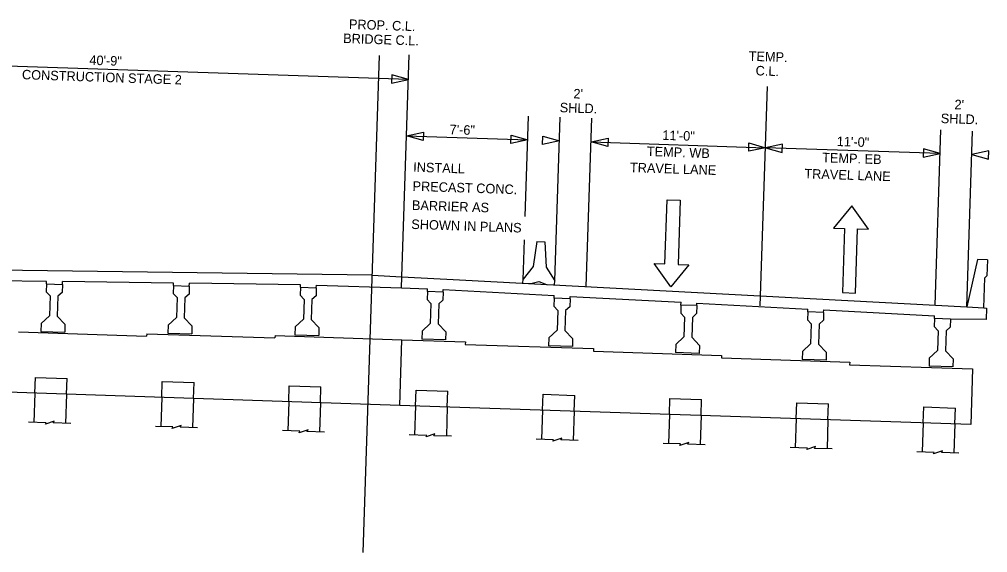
# Model space of a CAD drawing. Extents: x 977258 to 978774, y 1525946 to 1526932.
# Drawn here: x 977645 to 978255, y 1526136 to 1526472 of the extents above; entities that cross this region are included whole.
import ezdxf

# ---------------------------------------------------------------- set-up
doc = ezdxf.new("R2010")
doc.units = 0
for name, color, linetype in [('B_County and Route', 7, 'Continuous'), ('BDR_Plan Profile Grid 1', 7, 'Continuous'), ('BDR_Plan Profile Grid 5', 7, 'Continuous'), ('BDR_Plan Profile Grid 6', 7, 'Continuous'), ('Default', 7, 'Continuous'), ('R_Border', 7, 'Continuous'), ('R_MOT', 7, 'Continuous'), ('STAMP_PP', 7, 'Continuous')]:
    doc.layers.add(name, color=color, linetype=linetype)

msp = doc.modelspace()

# ---------------------------------------------------------------- linework, layer by layer
at = {"layer": 'B_County and Route'}
for p, q in [((977861.46, 1526135.95), (977871.9, 1526448.95)), ((978111.78, 1526291.34), (978116.39, 1526429.43))]:
    msp.add_line(p, q, dxfattribs=at)
at = {"layer": 'BDR_Plan Profile Grid 1'}
for p, q in [((977661.69, 1526217.73), (977650.75, 1526218.1)), ((977666.88, 1526218.68), (977661.27, 1526216.79)), ((977661.27, 1526216.79), (977661.69, 1526217.73)), ((977666.18, 1526217.58), (977666.88, 1526218.68)), ((977677.24, 1526217.21), (977666.18, 1526217.58)), ((977741.64, 1526215.07), (977730.71, 1526215.43)), ((977746.84, 1526216.01), (977741.23, 1526214.12)), ((977741.23, 1526214.12), (977741.64, 1526215.07)), ((977746.14, 1526214.92), (977746.84, 1526216.01)), ((977757.2, 1526214.55), (977746.14, 1526214.92)), ((977821.6, 1526212.4), (977810.67, 1526212.76)), ((977826.79, 1526213.35), (977821.18, 1526211.45)), ((977821.18, 1526211.45), (977821.6, 1526212.4)), ((977826.09, 1526212.25), (977826.79, 1526213.35)), ((977837.15, 1526211.88), (977826.09, 1526212.25))]:
    msp.add_line(p, q, dxfattribs=at)
at = {"layer": 'BDR_Plan Profile Grid 5'}
for p, q in [((978248.66, 1526320.45), (978241.83, 1526290.66)), ((978254.91, 1526320.24), (978248.66, 1526320.45)), ((978254.91, 1526320.24), (978254.57, 1526310.25)), ((977867.29, 1526310.65), (977492.25, 1526315.66)), ((977662.04, 1526306.73), (977592.03, 1526307.66)), ((977661.99, 1526305.16), (977662.04, 1526306.73)), ((977671.98, 1526304.83), (977672.04, 1526306.59)), ((977742.05, 1526305.66), (977672.04, 1526306.59)), ((977742, 1526304.09), (977742.05, 1526305.66)), ((977751.99, 1526303.76), (977752.05, 1526305.53)), ((977822.06, 1526304.59), (977752.05, 1526305.53)), ((977867.29, 1526310.65), (977885.93, 1526309.66)), ((977885.93, 1526309.66), (977922.22, 1526307.72)), ((977922.22, 1526307.72), (978241.83, 1526290.66)), ((978252.65, 1526290.08), (978253.28, 1526309.04)), ((978254.57, 1526310.25), (978253.28, 1526309.04)), ((977661.99, 1526305.16), (977661.82, 1526300.16)), ((977661.99, 1526305.16), (977661.82, 1526300.16)), ((977661.82, 1526300.16), (977664.24, 1526297.58)), ((977661.82, 1526300.16), (977664.24, 1526297.58)), ((977661.99, 1526305.16), (977671.98, 1526304.83)), ((977661.99, 1526305.16), (977671.98, 1526304.83)), ((977671.82, 1526299.83), (977669.24, 1526297.41)), ((977671.82, 1526299.83), (977669.24, 1526297.41)), ((977671.98, 1526304.83), (977671.82, 1526299.83)), ((977671.98, 1526304.83), (977671.82, 1526299.83)), ((977671.98, 1526304.83), (977671.82, 1526299.83)), ((977671.98, 1526304.83), (977671.82, 1526299.83)), ((977742, 1526304.09), (977741.83, 1526299.1)), ((977742, 1526304.09), (977741.83, 1526299.1)), ((977742, 1526304.09), (977751.99, 1526303.76)), ((977742, 1526304.09), (977751.99, 1526303.76)), ((977751.99, 1526303.76), (977751.83, 1526298.76)), ((977751.99, 1526303.76), (977751.83, 1526298.76)), ((977751.99, 1526303.76), (977751.83, 1526298.76)), ((977751.99, 1526303.76), (977751.83, 1526298.76)), ((977822.01, 1526303.03), (977821.84, 1526298.03)), ((977822.01, 1526303.03), (977821.84, 1526298.03)), ((977822.01, 1526303.03), (977822.06, 1526304.59)), ((977822.01, 1526303.03), (977832, 1526302.69)), ((977822.01, 1526303.03), (977832, 1526302.69)), ((977832, 1526302.69), (977831.84, 1526297.7)), ((977832, 1526302.69), (977831.84, 1526297.7)), ((977832, 1526302.69), (977831.84, 1526297.7)), ((977832, 1526302.69), (977831.84, 1526297.7)), ((977832, 1526302.69), (977832.06, 1526304.46)), ((977832.06, 1526304.46), (977885.7, 1526302.67)), ((977885.7, 1526302.67), (977902.02, 1526302.12)), ((977901.97, 1526300.36), (977901.8, 1526295.36)), ((977901.97, 1526300.36), (977901.8, 1526295.36)), ((977901.97, 1526300.36), (977902.02, 1526302.12)), ((977911.96, 1526300.03), (977901.97, 1526300.36)), ((977911.96, 1526300.03), (977911.79, 1526295.03)), ((977911.96, 1526300.03), (977912.01, 1526301.59)), ((977912.01, 1526301.59), (977981.93, 1526297.86)), ((977664.24, 1526297.58), (977663.82, 1526285.09)), ((977664.24, 1526297.58), (977663.82, 1526285.09)), ((977669.24, 1526297.41), (977668.82, 1526284.92)), ((977669.24, 1526297.41), (977668.82, 1526284.92)), ((977741.83, 1526299.1), (977744.25, 1526296.51)), ((977741.83, 1526299.1), (977744.25, 1526296.51)), ((977744.25, 1526296.51), (977743.83, 1526284.02)), ((977744.25, 1526296.51), (977743.83, 1526284.02)), ((977749.25, 1526296.35), (977748.83, 1526283.85)), ((977749.25, 1526296.35), (977748.83, 1526283.85)), ((977751.83, 1526298.76), (977749.25, 1526296.35)), ((977751.83, 1526298.76), (977749.25, 1526296.35)), ((977821.84, 1526298.03), (977824.26, 1526295.45)), ((977821.84, 1526298.03), (977824.26, 1526295.45)), ((977824.26, 1526295.45), (977823.84, 1526282.95)), ((977824.26, 1526295.45), (977823.84, 1526282.95)), ((977829.25, 1526295.28), (977828.84, 1526282.79)), ((977829.25, 1526295.28), (977828.84, 1526282.79)), ((977831.84, 1526297.7), (977829.25, 1526295.28)), ((977831.84, 1526297.7), (977829.25, 1526295.28)), ((977901.8, 1526295.36), (977904.21, 1526292.78)), ((977911.79, 1526295.03), (977909.21, 1526292.61)), ((977981.87, 1526296.09), (977981.7, 1526291.1)), ((977981.87, 1526296.09), (977981.7, 1526291.1)), ((977981.87, 1526296.09), (977981.93, 1526297.86)), ((977991.86, 1526295.76), (977981.87, 1526296.09)), ((977991.86, 1526295.76), (977991.7, 1526290.76)), ((977991.86, 1526295.76), (977991.91, 1526297.33)), ((977991.91, 1526297.33), (978061.83, 1526293.59)), ((978061.77, 1526291.83), (978061.83, 1526293.59)), ((977904.21, 1526292.78), (977903.8, 1526280.29)), ((977909.21, 1526292.61), (977908.8, 1526280.12)), ((977981.7, 1526291.1), (977984.12, 1526288.51)), ((977984.12, 1526288.51), (977983.7, 1526276.02)), ((977989.11, 1526288.35), (977988.7, 1526275.86)), ((977991.7, 1526290.76), (977989.11, 1526288.35)), ((978061.77, 1526291.83), (978061.6, 1526286.83)), ((978061.77, 1526291.83), (978061.6, 1526286.83)), ((978071.76, 1526291.5), (978061.77, 1526291.83)), ((978071.76, 1526291.5), (978071.6, 1526286.5)), ((978071.76, 1526291.5), (978071.82, 1526293.06)), ((978071.82, 1526293.06), (978141.73, 1526289.33)), ((978141.67, 1526287.56), (978141.51, 1526282.57)), ((978141.67, 1526287.56), (978141.51, 1526282.57)), ((978141.67, 1526287.56), (978141.73, 1526289.33)), ((978151.67, 1526287.23), (978141.67, 1526287.56)), ((978151.67, 1526287.23), (978151.5, 1526282.23)), ((978151.67, 1526287.23), (978151.72, 1526288.8)), ((978151.72, 1526288.8), (978221.63, 1526285.06)), ((978252.65, 1526290.08), (978254.31, 1526289.99)), ((978254.31, 1526289.99), (978254.07, 1526282.71)), ((977658.66, 1526280.26), (977663.82, 1526285.09)), ((977658.66, 1526280.26), (977663.82, 1526285.09)), ((977673.65, 1526279.76), (977668.82, 1526284.92)), ((977673.65, 1526279.76), (977668.82, 1526284.92)), ((977738.67, 1526279.19), (977743.83, 1526284.02)), ((977738.67, 1526279.19), (977743.83, 1526284.02)), ((977753.66, 1526278.69), (977748.83, 1526283.85)), ((977753.66, 1526278.69), (977748.83, 1526283.85)), ((977818.68, 1526278.12), (977823.84, 1526282.95)), ((977818.68, 1526278.12), (977823.84, 1526282.95)), ((977833.67, 1526277.62), (977828.84, 1526282.79)), ((977833.67, 1526277.62), (977828.84, 1526282.79)), ((978061.6, 1526286.83), (978064.02, 1526284.25)), ((978064.02, 1526284.25), (978063.6, 1526271.76)), ((978069.02, 1526284.08), (978068.6, 1526271.59)), ((978071.6, 1526286.5), (978069.02, 1526284.08)), ((978141.51, 1526282.57), (978143.92, 1526279.98)), ((978151.5, 1526282.23), (978148.92, 1526279.82)), ((978221.57, 1526283.3), (978221.41, 1526278.3)), ((978221.57, 1526283.3), (978221.41, 1526278.3)), ((978221.57, 1526283.3), (978221.63, 1526285.06)), ((978231.57, 1526282.96), (978221.57, 1526283.3)), ((978231.57, 1526282.96), (978231.4, 1526277.97)), ((978254.07, 1526282.71), (978231.57, 1526282.96)), ((977658.66, 1526280.26), (977658.49, 1526275.26)), ((977658.66, 1526280.26), (977658.49, 1526275.26)), ((977658.49, 1526275.26), (977673.48, 1526274.76)), ((977658.49, 1526275.26), (977673.48, 1526274.76)), ((977673.65, 1526279.76), (977673.48, 1526274.76)), ((977673.65, 1526279.76), (977673.48, 1526274.76)), ((977738.67, 1526279.19), (977738.5, 1526274.19)), ((977738.67, 1526279.19), (977738.5, 1526274.19)), ((977753.66, 1526278.69), (977753.49, 1526273.69)), ((977753.66, 1526278.69), (977753.49, 1526273.69)), ((977818.68, 1526278.12), (977818.51, 1526273.13)), ((977818.68, 1526278.12), (977818.51, 1526273.13)), ((977833.67, 1526277.62), (977833.5, 1526272.63)), ((977833.67, 1526277.62), (977833.5, 1526272.63)), ((977898.63, 1526275.46), (977898.47, 1526270.46)), ((977898.63, 1526275.46), (977903.8, 1526280.29)), ((977913.63, 1526274.96), (977908.8, 1526280.12)), ((977913.63, 1526274.96), (977913.46, 1526269.96)), ((977978.54, 1526271.19), (977983.7, 1526276.02)), ((977993.53, 1526270.69), (977988.7, 1526275.86)), ((978143.92, 1526279.98), (978143.5, 1526267.49)), ((978148.92, 1526279.82), (978148.5, 1526267.32)), ((978221.41, 1526278.3), (978223.82, 1526275.72)), ((978223.82, 1526275.72), (978223.41, 1526263.23)), ((978228.82, 1526275.55), (978228.4, 1526263.06)), ((978231.4, 1526277.97), (978228.82, 1526275.55)), ((977644.31, 1526274.9), (977725.1, 1526272.21)), ((977725.15, 1526273.8), (977725.1, 1526272.21)), ((977725.15, 1526273.8), (977805.94, 1526271.11)), ((977738.5, 1526274.19), (977753.49, 1526273.69)), ((977738.5, 1526274.19), (977753.49, 1526273.69)), ((977805.99, 1526272.71), (977805.94, 1526271.11)), ((977805.99, 1526272.71), (977885.94, 1526270.04)), ((977818.51, 1526273.13), (977833.5, 1526272.63)), ((977818.51, 1526273.13), (977833.5, 1526272.63)), ((977884.56, 1526228.67), (977885.94, 1526270.04)), ((977885.94, 1526270.04), (977925.92, 1526268.71)), ((977913.46, 1526269.96), (977898.47, 1526270.46)), ((977978.54, 1526271.19), (977978.37, 1526266.19)), ((977993.53, 1526270.69), (977993.36, 1526265.69)), ((978058.44, 1526266.93), (978063.6, 1526271.76)), ((978073.43, 1526266.43), (978068.6, 1526271.59)), ((977925.92, 1526268.71), (977925.87, 1526267.11)), ((977925.87, 1526267.11), (978006.66, 1526264.42)), ((977993.36, 1526265.69), (977978.37, 1526266.19)), ((978006.66, 1526264.42), (978006.6, 1526262.82)), ((978006.6, 1526262.82), (978087.39, 1526260.12)), ((978058.44, 1526266.93), (978058.27, 1526261.93)), ((978073.43, 1526266.43), (978073.26, 1526261.43)), ((978138.34, 1526262.66), (978143.5, 1526267.49)), ((978153.33, 1526262.16), (978148.5, 1526267.32)), ((978218.24, 1526258.39), (978223.41, 1526263.23)), ((978233.23, 1526257.89), (978228.4, 1526263.06)), ((978073.26, 1526261.43), (978058.27, 1526261.93)), ((978087.39, 1526260.12), (978087.34, 1526258.52)), ((978087.34, 1526258.52), (978168.13, 1526255.83)), ((978138.34, 1526262.66), (978138.17, 1526257.66)), ((978153.17, 1526257.16), (978138.17, 1526257.66)), ((978153.33, 1526262.16), (978153.17, 1526257.16)), ((978218.24, 1526258.39), (978218.08, 1526253.4)), ((978233.23, 1526257.89), (978233.07, 1526252.9)), ((978168.13, 1526255.83), (978168.07, 1526254.23)), ((978168.07, 1526254.23), (978245.53, 1526251.65)), ((978233.07, 1526252.9), (978218.08, 1526253.4)), ((978245.53, 1526251.65), (978244.36, 1526216.67)), ((977884.56, 1526228.67), (977484.79, 1526242)), ((977654.69, 1526236.33), (977654.08, 1526217.99)), ((977674.68, 1526235.67), (977674.07, 1526217.32)), ((977734.65, 1526233.67), (977734.04, 1526215.32)), ((977754.64, 1526233), (977754.03, 1526214.65)), ((977814.6, 1526231), (977813.99, 1526212.65)), ((977834.59, 1526230.33), (977833.98, 1526211.99)), ((978244.36, 1526216.67), (977884.56, 1526228.67)), ((977894.56, 1526228.33), (977893.95, 1526209.99)), ((977914.55, 1526227.67), (977913.94, 1526209.32)), ((977974.51, 1526225.67), (977973.9, 1526207.32)), ((977994.5, 1526225), (977993.89, 1526206.65)), ((978054.47, 1526223), (978053.86, 1526204.65)), ((978074.46, 1526222.33), (978073.85, 1526203.99)), ((978134.43, 1526220.33), (978133.81, 1526201.99)), ((978154.41, 1526219.67), (978153.8, 1526201.32)), ((978214.38, 1526217.67), (978213.77, 1526199.32)), ((978234.37, 1526217), (978233.76, 1526198.66)), ((977901.56, 1526209.73), (977890.62, 1526210.1)), ((977906.75, 1526210.68), (977901.14, 1526208.79)), ((977901.14, 1526208.79), (977901.56, 1526209.73)), ((977906.05, 1526209.58), (977906.75, 1526210.68)), ((977917.11, 1526209.21), (977906.05, 1526209.58)), ((977986.71, 1526208.02), (977981.09, 1526206.12)), ((977986, 1526206.92), (977986.71, 1526208.02)), ((977981.51, 1526207.07), (977970.58, 1526207.43)), ((977981.09, 1526206.12), (977981.51, 1526207.07)), ((977997.06, 1526206.55), (977986, 1526206.92)), ((978061.47, 1526204.4), (978050.53, 1526204.77)), ((978066.66, 1526205.35), (978061.05, 1526203.45)), ((978061.05, 1526203.45), (978061.47, 1526204.4)), ((978065.96, 1526204.25), (978066.66, 1526205.35)), ((978077.02, 1526203.88), (978065.96, 1526204.25)), ((978141.42, 1526201.73), (978130.49, 1526202.1)), ((978146.62, 1526202.68), (978141.01, 1526200.79)), ((978141.01, 1526200.79), (978141.42, 1526201.73)), ((978145.91, 1526201.58), (978146.62, 1526202.68)), ((978156.98, 1526201.22), (978145.91, 1526201.58)), ((978221.38, 1526199.07), (978210.44, 1526199.43)), ((978226.57, 1526200.02), (978220.96, 1526198.12)), ((978220.96, 1526198.12), (978221.38, 1526199.07)), ((978225.87, 1526198.92), (978226.57, 1526200.02)), ((978236.93, 1526198.55), (978225.87, 1526198.92))]:
    msp.add_line(p, q, dxfattribs=at)
at = {"layer": 'BDR_Plan Profile Grid 6'}
for p, q in [((977885.7, 1526302.67), (977885.93, 1526309.66)), ((978241.83, 1526290.66), (978252.65, 1526290.08)), ((977654.69, 1526236.33), (977655.03, 1526246.33)), ((977655.03, 1526246.33), (977675.01, 1526245.66)), ((977674.68, 1526235.67), (977675.01, 1526245.66)), ((977734.65, 1526233.67), (977734.98, 1526243.66)), ((977734.98, 1526243.66), (977754.97, 1526242.99)), ((977754.64, 1526233), (977754.97, 1526242.99)), ((977814.6, 1526231), (977814.94, 1526240.99)), ((977814.94, 1526240.99), (977834.93, 1526240.33)), ((977834.59, 1526230.33), (977834.93, 1526240.33)), ((977894.56, 1526228.33), (977894.89, 1526238.33)), ((977894.89, 1526238.33), (977914.88, 1526237.66)), ((977914.55, 1526227.67), (977914.88, 1526237.66)), ((977974.51, 1526225.67), (977974.85, 1526235.66)), ((977974.85, 1526235.66), (977994.84, 1526234.99)), ((977994.5, 1526225), (977994.84, 1526234.99)), ((978054.47, 1526223), (978054.8, 1526232.99)), ((978054.8, 1526232.99), (978074.79, 1526232.33)), ((978074.46, 1526222.33), (978074.79, 1526232.33)), ((978134.43, 1526220.33), (978134.76, 1526230.33)), ((978134.76, 1526230.33), (978154.75, 1526229.66)), ((978154.41, 1526219.67), (978154.75, 1526229.66)), ((978214.38, 1526217.67), (978214.71, 1526227.66)), ((978214.71, 1526227.66), (978234.7, 1526227)), ((978234.37, 1526217), (978234.7, 1526227))]:
    msp.add_line(p, q, dxfattribs=at)
at = {"layer": 'Default'}
for points in [[(978066.8, 1526317.21), (978055.33, 1526303.31), (978044.82, 1526317.95), (978051.69, 1526317.72), (978053.04, 1526358.15), (978061.28, 1526357.88), (978059.93, 1526317.44)], [(978179.94, 1526339.63), (978169.42, 1526354.27), (978157.95, 1526340.37), (978164.82, 1526340.14), (978163.47, 1526299.7), (978171.72, 1526299.43), (978173.07, 1526339.86)]]:
    msp.add_lwpolyline(points, close=True, dxfattribs=at)
at = {"layer": 'R_MOT'}
for p, q in [((977971.06, 1526331.87), (977968.55, 1526316.14)), ((977971.06, 1526331.87), (977971.03, 1526331.29)), ((977971.06, 1526331.87), (977976.05, 1526331.6)), ((977976.05, 1526331.6), (977976.87, 1526315.7)), ((977968.55, 1526316.14), (977962.28, 1526308.13)), ((977976.87, 1526315.7), (977982.25, 1526307.07)), ((977962.15, 1526305.64), (977962.28, 1526308.13)), ((977962.15, 1526305.64), (977962.15, 1526305.64)), ((977962.15, 1526305.64), (977967.14, 1526305.37)), ((977967.14, 1526305.37), (977972.22, 1526306.77)), ((977972.22, 1526306.77), (977977.13, 1526304.84)), ((977982.12, 1526304.57), (977982.25, 1526307.07)), ((977977.13, 1526304.84), (977982.12, 1526304.57))]:
    msp.add_line(p, q, dxfattribs=at)
at = {"layer": 'STAMP_PP'}
for p, q in [((977890.07, 1526433.83), (977484.13, 1526447.37)), ((977885.93, 1526309.66), (977890.59, 1526449.39)), ((977963.6, 1526347.68), (977965.7, 1526410.78)), ((977982.23, 1526307.1), (977985.67, 1526410.11)), ((978002.12, 1526303.46), (978005.66, 1526409.45)), ((977888.89, 1526398.49), (977965.21, 1526395.94)), ((978221.85, 1526291.73), (978225.54, 1526402.12)), ((978241.83, 1526290.66), (978245.52, 1526401.45)), ((978005.16, 1526394.61), (978115.1, 1526390.95)), ((978225.04, 1526387.28), (978115.1, 1526390.95)), ((977962.27, 1526307.76), (977963.11, 1526332.91))]:
    msp.add_line(p, q, dxfattribs=at)
for points in [[(977879.43, 1526431.54), (977890.07, 1526433.83), (977879.61, 1526436.82)], [(977899.36, 1526395.5), (977888.89, 1526398.49), (977899.54, 1526400.78)], [(977954.74, 1526398.93), (977965.21, 1526395.94), (977954.57, 1526393.66)], [(977974.71, 1526398.27), (977985.17, 1526395.28), (977974.53, 1526392.99)], [(978015.63, 1526391.62), (978005.16, 1526394.61), (978015.81, 1526396.9)], [(978104.64, 1526393.94), (978115.1, 1526390.95), (978104.46, 1526388.66)], [(978125.74, 1526393.23), (978115.1, 1526390.95), (978125.57, 1526387.96)], [(978214.4, 1526384.99), (978225.04, 1526387.28), (978214.57, 1526390.27)], [(978255.67, 1526388.9), (978245.03, 1526386.61), (978255.5, 1526383.62)]]:
    msp.add_lwpolyline(points, close=True, dxfattribs=at)

# ---------------------------------------------------------------- texts
at = {"layer": 'R_Border'}
for s, p in [('PROP. C.L.', (977852.49, 1526465.77)), ('BRIDGE C.L.', (977848.84, 1526456.89)), ('40\'-9"', (977688.94, 1526443.15)), ('TEMP.', (978104.37, 1526445.68)), ('CONSTRUCTION STAGE 2', (977646.47, 1526434.06)), ('C.L.', (978108.75, 1526436.53)), ("2' ", (977993.96, 1526422.01)), ('SHLD.', (977985.3, 1526413.3)), ("2' ", (978234.06, 1526415.18)), ('SHLD.', (978225.4, 1526406.47)), ('7\'-6"', (977915.91, 1526399.46)), ('11\'-0"', (978049.96, 1526395.91)), ('11\'-0"', (978159.89, 1526392)), ('TEMP. WB', (978040.21, 1526385.73)), ('TEMP. EB', (978150.66, 1526381.8)), ('INSTALL ', (977892.98, 1526375.79)), ('TRAVEL LANE', (978029.54, 1526375.58)), ('TRAVEL LANE', (978139.47, 1526371.67)), ('PRECAST CONC.', (977892.58, 1526363.8)), ('BARRIER AS ', (977892.18, 1526351.81)), ('SHOWN IN PLANS', (977891.78, 1526339.81))]:
    msp.add_text(s, height=6, rotation=358.09005, dxfattribs=at).set_placement(p)

doc.saveas('drawing.dxf')
